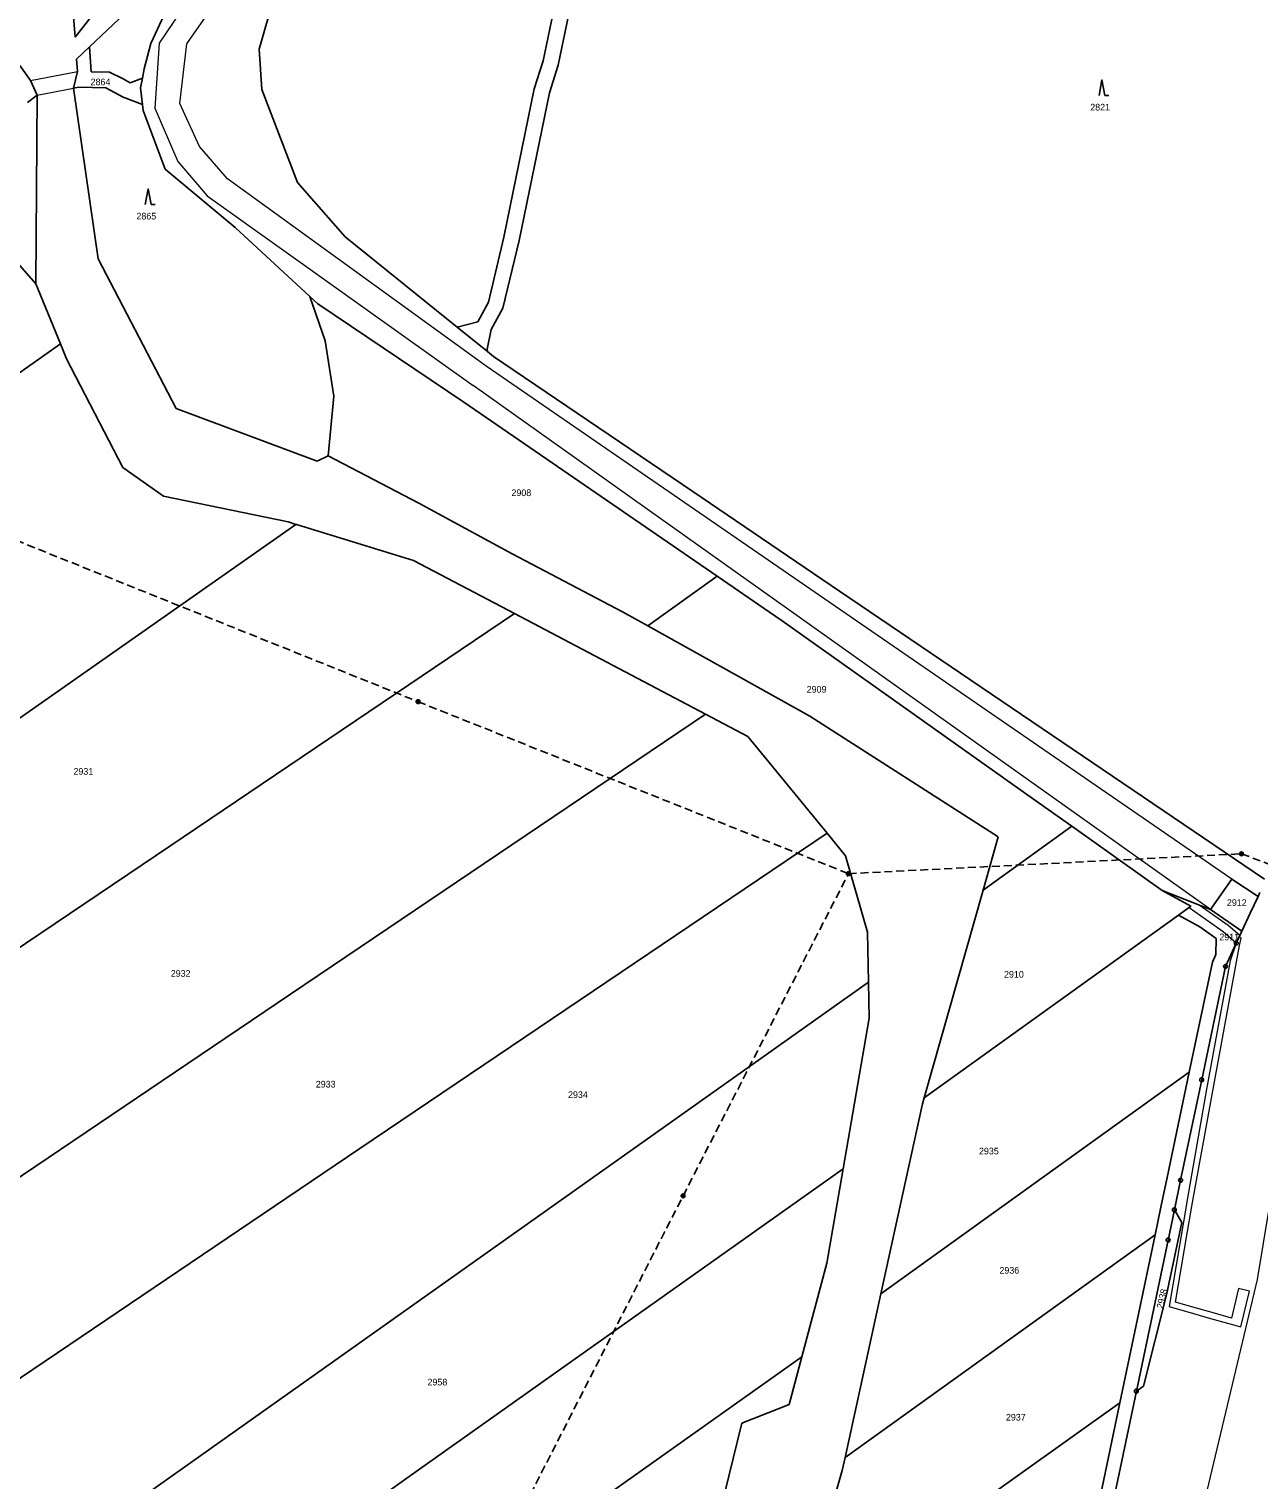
# Model space of a CAD drawing. Extents: x -606517 to -602431, y -1183120 to -1179397.
# Drawn here: x -605135.8 to -604821.3, y -1182125.3 to -1181754.3 of the extents above; entities that cross this region are included whole.
import ezdxf

# ---------------------------------------------------------------- set-up
doc = ezdxf.new("R2010")
doc.units = 0
doc.header["$LTSCALE"] = 0.68
doc.linetypes.add('MEDIUM_DASHED', pattern=[4.5, 3, -1.5])
for name, color, linetype, lineweight in [('1', 7, 'Continuous', 25), ('13', 7, 'Continuous', 13), ('3', 7, 'Continuous', 25), ('4', 7, 'Continuous', 13), ('6', 7, 'Continuous', 25), ('8', 7, 'Continuous', 25)]:
    doc.layers.add(name, color=color, linetype=linetype, lineweight=lineweight)
doc.layers.add('2', color=7, linetype='Continuous')

msp = doc.modelspace()

# ---------------------------------------------------------------- linework, layer by layer
at = {"layer": '1'}
for p, q in [((-605124.07, -1181756.39), (-605110.04, -1181738.63)), ((-605070.6, -1181736.9), (-605077, -1181759.5)), ((-605101.61, -1181741.09), (-605120.37, -1181758.94)), ((-605000.91, -1181745.64), (-605004.36, -1181762.51)), ((-605000.5, -1181763.59), (-604996.96, -1181746.3)), ((-605124.44, -1181751.22), (-605124.07, -1181756.39)), ((-605104.71, -1181758.04), (-605101.38, -1181750.88)), ((-605120.37, -1181758.94), (-605123.66, -1181762.08)), ((-605119.93, -1181765.29), (-605120.37, -1181758.94)), ((-605106.41, -1181764.53), (-605104.71, -1181758.04)), ((-605077, -1181759.5), (-605076.3, -1181769.8)), ((-605135.46, -1181767.53), (-605138.21, -1181763.66)), ((-605123.66, -1181762.08), (-605123.44, -1181765.2)), ((-605106.86, -1181766.91), (-605106.41, -1181764.53)), ((-605004.36, -1181762.51), (-605006.66, -1181769.65)), ((-605002.78, -1181770.64), (-605000.5, -1181763.59)), ((-605133.79, -1181771.28), (-605135.46, -1181767.53)), ((-605123.44, -1181765.2), (-605124.45, -1181769.46)), ((-605115.27, -1181765.4), (-605119.93, -1181765.29)), ((-605111.75, -1181767.11), (-605115.27, -1181765.4)), ((-605109.99, -1181768.15), (-605111.75, -1181767.11)), ((-605106.86, -1181766.91), (-605109.99, -1181768.15)), ((-605107.33, -1181769.37), (-605106.86, -1181766.91)), ((-605133.79, -1181771.28), (-605136.23, -1181773.11)), ((-605134.06, -1181819.54), (-605133.79, -1181771.28)), ((-605123.11, -1181769.21), (-605124.45, -1181769.46)), ((-605116.24, -1181769.38), (-605123.11, -1181769.21)), ((-605111.78, -1181771.74), (-605116.24, -1181769.38)), ((-605106.83, -1181773.67), (-605111.78, -1181771.74)), ((-605106.83, -1181773.67), (-605107.33, -1181769.37)), ((-605076.3, -1181769.8), (-605067.2, -1181793.6)), ((-605006.66, -1181769.65), (-605014.39, -1181807.57)), ((-605010.49, -1181808.44), (-605002.78, -1181770.64)), ((-605106.65, -1181775.23), (-605106.83, -1181773.67)), ((-605100.99, -1181790.24), (-605106.65, -1181775.23)), ((-605083.11, -1181805.09), (-605100.99, -1181790.24)), ((-605067.2, -1181793.6), (-605055, -1181807.5)), ((-605064.02, -1181822.78), (-605083.11, -1181805.09)), ((-605055, -1181807.5), (-605026.36, -1181830.59)), ((-605014.39, -1181807.57), (-605018.38, -1181824.26)), ((-605014.65, -1181825.77), (-605010.49, -1181808.44)), ((-605141.14, -1181811.45), (-605134.06, -1181819.54)), ((-605134.06, -1181819.54), (-605127.8, -1181834.91)), ((-605064.02, -1181822.78), (-605062.01, -1181824.64)), ((-605060.15, -1181834.14), (-605064.02, -1181822.78)), ((-605018.38, -1181824.26), (-605021.12, -1181829.23)), ((-605062.01, -1181824.64), (-605024.63, -1181849.84)), ((-605017.65, -1181831.23), (-605014.65, -1181825.77)), ((-605021.12, -1181829.23), (-605026.36, -1181830.59)), ((-605026.36, -1181830.59), (-605018.64, -1181836.82)), ((-605018.7, -1181836.28), (-605017.65, -1181831.23)), ((-605127.8, -1181834.91), (-605226.39, -1181904.12)), ((-605127.8, -1181834.91), (-605126.23, -1181838.75)), ((-605057.92, -1181848.23), (-605060.15, -1181834.14)), ((-605126.23, -1181838.75), (-605111.82, -1181866.56)), ((-605018.64, -1181836.82), (-605018.7, -1181836.28)), ((-605018.64, -1181836.82), (-605017.05, -1181838.1)), ((-605017.05, -1181838.1), (-604966.1, -1181872.67)), ((-605059.31, -1181863.5), (-605057.92, -1181848.23)), ((-605024.63, -1181849.84), (-604959.84, -1181894.35)), ((-605098.19, -1181851.41), (-605062.13, -1181864.94)), ((-605062.13, -1181864.94), (-605059.31, -1181863.5)), ((-605036.16, -1181875.61), (-605059.31, -1181863.5)), ((-605111.82, -1181866.56), (-605101.45, -1181873.89)), ((-605101.45, -1181873.89), (-605069.6, -1181880.46)), ((-605012.27, -1181888.58), (-605036.16, -1181875.61)), ((-604966.1, -1181872.67), (-604928.6, -1181898.12)), ((-605207.19, -1181979.02), (-605067.65, -1181881.06)), ((-605069.6, -1181880.46), (-605067.65, -1181881.06)), ((-605067.65, -1181881.06), (-605067.42, -1181881.13)), ((-605067.42, -1181881.13), (-605037.5, -1181890.32)), ((-605037.5, -1181890.32), (-605011.73, -1181903.89)), ((-604984.1, -1181903.42), (-605012.27, -1181888.58)), ((-604959.84, -1181894.35), (-604977.62, -1181907.04)), ((-604946.5, -1181903.51), (-604959.84, -1181894.35)), ((-604928.6, -1181898.12), (-604819.96, -1181971.83)), ((-605011.73, -1181903.89), (-605103.24, -1181965.68)), ((-605011.73, -1181903.89), (-604962.9, -1181929.61)), ((-604977.62, -1181907.04), (-604984.1, -1181903.42)), ((-604943.29, -1181905.78), (-604946.5, -1181903.51)), ((-604878.96, -1181951.38), (-604943.29, -1181905.78)), ((-604977.62, -1181907.04), (-604936.19, -1181930.15)), ((-604962.9, -1181929.61), (-605072.42, -1182003.56)), ((-604962.9, -1181929.61), (-604952.06, -1181935.32)), ((-604936.19, -1181930.15), (-604888.05, -1181960.99)), ((-604952.06, -1181935.32), (-604931.77, -1181960.11)), ((-604869.22, -1181958.3), (-604878.96, -1181951.38)), ((-604931.77, -1181960.11), (-605051.22, -1182040.78)), ((-604931.77, -1181960.11), (-604927.03, -1181965.9)), ((-604869.22, -1181958.3), (-604891.9, -1181974.61)), ((-604888.05, -1181960.99), (-604891.9, -1181974.61)), ((-604846.07, -1181974.76), (-604869.22, -1181958.3)), ((-605103.24, -1181965.68), (-605194.76, -1182027.48)), ((-604927.03, -1181965.9), (-604921.47, -1181985.37)), ((-604828.29, -1181971.81), (-604833.72, -1181979.59)), ((-604821.56, -1181976.25), (-604828.29, -1181971.81)), ((-604891.9, -1181974.61), (-604906.93, -1182027.75)), ((-604838.76, -1181978.75), (-604846.07, -1181974.76)), ((-604833.72, -1181979.59), (-604846.07, -1181974.76)), ((-604823.57, -1181980.55), (-604821.56, -1181976.25)), ((-604821.1, -1181975.25), (-604821.56, -1181976.25)), ((-604841.92, -1181981.01), (-604838.76, -1181978.75)), ((-604833.72, -1181979.59), (-604825.72, -1181985.17)), ((-604841.92, -1181981.01), (-604906.93, -1182027.75)), ((-604836.42, -1181984.01), (-604841.92, -1181981.01)), ((-604825.72, -1181985.17), (-604823.57, -1181980.55)), ((-604921.47, -1181985.37), (-604921.18, -1181998.17)), ((-604832.28, -1181987.04), (-604836.42, -1181984.01)), ((-604832.34, -1181991.08), (-604832.28, -1181987.04)), ((-604827.14, -1181988.21), (-604825.72, -1181985.17)), ((-604833.24, -1181993.04), (-604832.34, -1181991.08)), ((-604829.9, -1181994.15), (-604827.14, -1181988.21)), ((-604839.15, -1182021.2), (-604833.24, -1181993.04)), ((-604835.98, -1182023.16), (-604829.9, -1181994.15)), ((-605040.11, -1182082.51), (-604921.18, -1181998.17)), ((-604921.18, -1181998.17), (-604920.97, -1182007.36)), ((-605072.42, -1182003.56), (-605181.94, -1182077.52)), ((-604920.97, -1182007.36), (-604927.66, -1182045.95)), ((-604918.01, -1182077.9), (-604839.15, -1182021.2)), ((-604844.8, -1182048.13), (-604839.15, -1182021.2)), ((-604841.37, -1182048.85), (-604835.98, -1182023.16)), ((-604906.93, -1182027.75), (-604907.37, -1182029.3)), ((-604907.37, -1182029.3), (-604918.01, -1182077.9)), ((-605051.22, -1182040.78), (-605170.68, -1182121.44)), ((-605038.66, -1182124.68), (-604927.66, -1182045.95)), ((-604927.66, -1182045.95), (-604931.84, -1182070.05)), ((-604846.4, -1182055.73), (-604844.8, -1182048.13)), ((-604842.97, -1182056.45), (-604841.37, -1182048.85)), ((-604847.88, -1182062.81), (-604846.4, -1182055.73)), ((-604844.58, -1182064.15), (-604842.97, -1182056.45)), ((-604842.97, -1182056.45), (-604841.02, -1182059.63)), ((-604841.02, -1182059.63), (-604845.02, -1182078.14)), ((-604927.18, -1182119.81), (-604847.88, -1182062.81)), ((-604856.9, -1182105.79), (-604847.88, -1182062.81)), ((-604852.69, -1182102.79), (-604844.58, -1182064.15)), ((-604931.84, -1182070.05), (-604938.2, -1182094.02)), ((-604918.01, -1182077.9), (-604927.18, -1182119.81)), ((-604845.02, -1182078.14), (-604850.87, -1182101.5)), ((-605159.04, -1182166.85), (-605040.11, -1182082.51)), ((-605039.54, -1182165.88), (-604938.2, -1182094.02)), ((-604938.2, -1182094.02), (-604941.44, -1182106.2)), ((-604850.87, -1182101.5), (-604852.69, -1182102.79)), ((-604941.44, -1182106.2), (-604953.58, -1182111)), ((-604856.9, -1182105.79), (-604907.5, -1182141.89)), ((-604865.51, -1182146.87), (-604856.9, -1182105.79)), ((-604862.9, -1182151.5), (-604852.69, -1182102.79)), ((-604953.58, -1182111), (-604961.91, -1182144.88)), ((-604927.18, -1182119.81), (-604927.9, -1182123.09)), ((-605149.67, -1182203.4), (-605038.66, -1182124.68)), ((-604927.9, -1182123.09), (-604939.94, -1182165.02))]:
    msp.add_line(p, q, dxfattribs=at)
msp.add_lwpolyline([(-605124.45, -1181769.46), (-605118.18, -1181813.16), (-605098.19, -1181851.41)], dxfattribs=at)
at = {"layer": '13'}
for points in [[(-604846.07, -1181974.76), (-604842.79, -1181976.55), (-604838.76, -1181978.75), (-604839.22, -1181979.08), (-604830.46, -1181985.26), (-604827.12, -1181988.17), (-604826.24, -1181986.28), (-604829.22, -1181983.69), (-604836.64, -1181978.45), (-604837.59, -1181978.08), (-604843.44, -1181975.79), (-604844.39, -1181975.42)], [(-604826.28, -1181988.82), (-604825.92, -1181986.89), (-604826.35, -1181986.52), (-604827.14, -1181988.21), (-604828.68, -1181992.75), (-604834.73, -1182025.52), (-604839.47, -1182052.45), (-604840.76, -1182060.05), (-604844.34, -1182081.14), (-604838.06, -1182082.94), (-604833.69, -1182084.19), (-604825.97, -1182086.4), (-604823.76, -1182077.22), (-604826.57, -1182076.55), (-604828.4, -1182084.14), (-604833.34, -1182082.73), (-604837.66, -1182081.49), (-604842.65, -1182080.06), (-604839.61, -1182061.94), (-604838.37, -1182054.54), (-604833.48, -1182027.87), (-604828.35, -1182000.01)]]:
    msp.add_lwpolyline(points, close=True, dxfattribs=at)
at = {"layer": '3'}
for p, q in [((-604860.73, -1181771.36), (-604859.734, -1181771.36)), ((-605104.62, -1181799.24), (-605103.624, -1181799.24))]:
    msp.add_line(p, q, dxfattribs=at)
for points in [[(-604860.73, -1181771.36), (-604861.48, -1181767.36), (-604862.23, -1181771.36)], [(-605104.62, -1181799.24), (-605105.37, -1181795.24), (-605106.12, -1181799.24)]]:
    msp.add_lwpolyline(points, dxfattribs=at)
at = {"layer": '4'}
for p, q in [((-605135.46, -1181767.53), (-605123.44, -1181765.2)), ((-605133.79, -1181771.28), (-605124.45, -1181769.46)), ((-604828.29, -1181971.81), (-605018.92, -1181840.57)), ((-604833.72, -1181979.59), (-605022.26, -1181845.54))]:
    msp.add_line(p, q, dxfattribs=at)
for points in [[(-604978.57, -1181618.96), (-605088.61, -1181737.28), (-605102.58, -1181757.94), (-605103.67, -1181774.56), (-605097.81, -1181788.27), (-605090.28, -1181797.02), (-605022.26, -1181845.54)], [(-605092.24, -1181784.38), (-605097.29, -1181773.41), (-605095.53, -1181758.12), (-605083.38, -1181740.77)], [(-605018.92, -1181840.57), (-605085.05, -1181792.66), (-605092.24, -1181784.38)], [(-604808.55, -1182014.89), (-604818.73, -1182055.62), (-604821.76, -1182074.24)], [(-604821.76, -1182074.24), (-604841.05, -1182155.14), (-604865.19, -1182211.29)]]:
    msp.add_lwpolyline(points, dxfattribs=at)
at = {"layer": '6', "linetype": 'MEDIUM_DASHED'}
for p, q in [((-605147.65, -1181881.73), (-605036.35, -1181926.43)), ((-605036.35, -1181926.43), (-604926.3, -1181970.43)), ((-604825.79, -1181965.35), (-604737.51, -1181998.96))]:
    msp.add_line(p, q, dxfattribs=at)
msp.add_lwpolyline([(-605110.59, -1182329.36), (-605061.79, -1182234.37), (-605014.59, -1182142.85), (-604968.59, -1182052.84), (-604926.3, -1181970.43), (-604825.79, -1181965.35)], dxfattribs=at)
at = {"layer": '6'}
for centre, radius in [((-605036.3534, -1181926.4299), 0.5), ((-605036.3534, -1181926.4299), 0.4), ((-605036.3534, -1181926.4299), 0.3), ((-605036.3534, -1181926.4299), 0.2), ((-605036.3534, -1181926.4299), 0.1), ((-604825.7934, -1181965.3499), 0.5), ((-604825.7934, -1181965.3499), 0.4), ((-604825.7934, -1181965.3499), 0.3), ((-604825.7934, -1181965.3499), 0.2), ((-604825.7934, -1181965.3499), 0.1), ((-604926.3034, -1181970.4299), 0.5), ((-604926.3034, -1181970.4299), 0.4), ((-604926.3034, -1181970.4299), 0.3), ((-604926.3034, -1181970.4299), 0.2), ((-604926.3034, -1181970.4299), 0.1), ((-604968.5934, -1182052.8399), 0.5), ((-604968.5934, -1182052.8399), 0.4), ((-604968.5934, -1182052.8399), 0.3), ((-604968.5934, -1182052.8399), 0.2), ((-604968.5934, -1182052.8399), 0.1)]:
    msp.add_circle(centre, radius, dxfattribs=at)
at = {"layer": '8'}
for centre, radius in [((-604827.14, -1181988.2099), 0.5), ((-604827.14, -1181988.2099), 0.0303), ((-604829.9, -1181994.1499), 0.5), ((-604829.9, -1181994.1499), 0.0303), ((-604835.98, -1182023.1599), 0.5), ((-604835.98, -1182023.1599), 0.0303), ((-604841.37, -1182048.8499), 0.5), ((-604841.37, -1182048.8499), 0.0303), ((-604842.97, -1182056.4499), 0.5), ((-604842.97, -1182056.4499), 0.0303), ((-604844.58, -1182064.1499), 0.5), ((-604844.58, -1182064.1499), 0.0303), ((-604852.69, -1182102.7899), 0.5), ((-604852.69, -1182102.7899), 0.0303)]:
    msp.add_circle(centre, radius, dxfattribs=at)

# ---------------------------------------------------------------- texts
at = {"layer": '2'}
for s, p in [('2864', (-605120.1, -1181768.735)), ('2821', (-604864.48, -1181775.185)), ('2865', (-605108.37, -1181803.065)), ('2908', (-605012.48, -1181873.835)), ('2909', (-604936.98, -1181924.125)), ('2931', (-605124.48, -1181945.125)), ('2912', (-604829.53, -1181978.685)), ('2911', (-604831.47, -1181987.485)), ('2932', (-605099.6, -1181996.805)), ('2910', (-604886.53, -1181997.035)), ('2933', (-605062.51, -1182025.135)), ('2934', (-604998.01, -1182027.815)), ('2935', (-604892.93, -1182042.255)), ('2936', (-604887.7, -1182072.755)), ('2958', (-605033.95, -1182101.355)), ('2937', (-604886.04, -1182110.335))]:
    msp.add_text(s, height=1.7, dxfattribs=at).set_placement(p)
msp.add_text('2938', height=1.7, rotation=77, dxfattribs=at).set_placement((-604845.905, -1182081.815))

doc.saveas('drawing.dxf')
